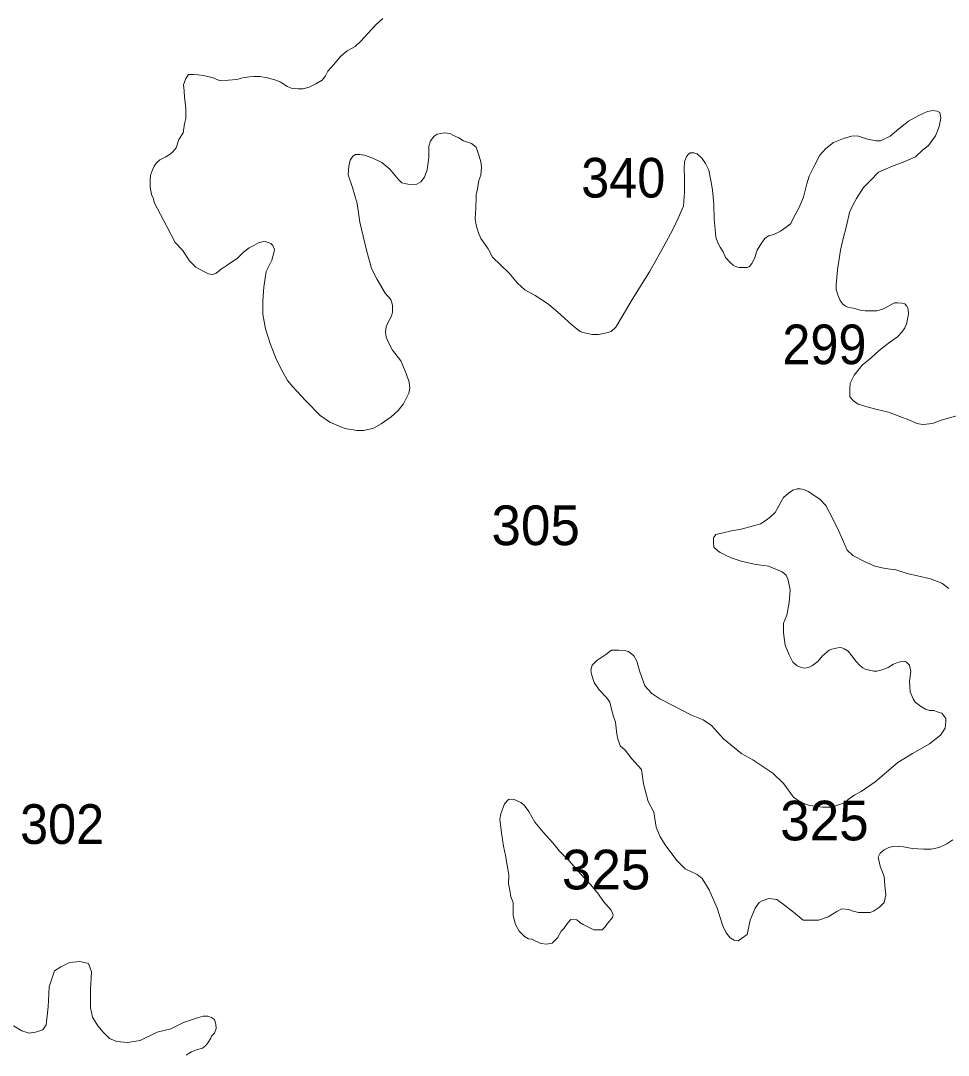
# Model space of a CAD drawing. Extents: x 445.4 to 500, y 8728.7 to 8784.
# Drawn here: x 451.345 to 455.087, y 8728.683 to 8732.857 of the extents above; entities that cross this region are included whole.
import ezdxf

# ---------------------------------------------------------------- set-up
doc = ezdxf.new("R2010")
doc.units = 0
doc.header["$LTSCALE"] = 0.064
doc.layers.add('2', color=7, linetype='Continuous', lineweight=13)
doc.layers.add('21', color=7, linetype='Continuous')

msp = doc.modelspace()

# ---------------------------------------------------------------- linework, layer by layer
at = {"layer": '2'}
for points in [[(452.8059, 8732.8655), (452.7772, 8732.84), (452.7453, 8732.805), (452.7166, 8732.7748), (452.6943, 8732.7525), (452.6624, 8732.735), (452.6369, 8732.7143), (452.6073, 8732.6783), (452.5834, 8732.6529), (452.5738, 8732.6338), (452.5611, 8732.6163), (452.5356, 8732.602), (452.5085, 8732.5892), (452.4846, 8732.5813), (452.4638, 8732.5813), (452.4399, 8732.5829), (452.4192, 8732.5908), (452.3937, 8732.6083), (452.3698, 8732.6179), (452.3411, 8732.6258), (452.3092, 8732.6322), (452.2852, 8732.6322), (452.2677, 8732.6306), (452.2406, 8732.6258), (452.2167, 8732.6195)], [(452.2167, 8732.6195), (452.1832, 8732.6163), (452.1497, 8732.6147), (452.121, 8732.6258), (452.0827, 8732.6354), (452.0588, 8732.6386), (452.0424, 8732.6399), (452.0212, 8732.6399), (452.0106, 8732.6229), (452.0021, 8732.5974), (452.0042, 8732.5741), (452.0063, 8732.5487), (452.0084, 8732.5275), (452.0106, 8732.4999), (452.0106, 8732.4618), (452.0063, 8732.4406), (451.9999, 8732.4045), (451.9829, 8732.3769), (451.9716, 8732.3442), (451.9588, 8732.3273), (451.9472, 8732.3178), (451.9303, 8732.3072), (451.9059, 8732.2956), (451.8921, 8732.284), (451.8837, 8732.2702), (451.8763, 8732.2554), (451.8689, 8732.2333), (451.8667, 8732.2121), (451.8678, 8732.1846), (451.872, 8732.1551), (451.8805, 8732.1382), (451.8837, 8732.1234), (451.9341, 8732.0259), (451.9681, 8731.9623), (451.9978, 8731.9305), (452.0254, 8731.8881), (452.0509, 8731.8627), (452.0807, 8731.8457), (452.1019, 8731.8351), (452.1189, 8731.833), (452.1316, 8731.8372), (452.1529, 8731.8542), (452.1784, 8731.8711), (452.2197, 8731.8981), (452.2432, 8731.9225), (452.2666, 8731.941), (452.2852, 8731.9498), (452.3048, 8731.9605), (452.3184, 8731.9644), (452.3311, 8731.9654), (452.339, 8731.9634), (452.3536, 8731.9585), (452.3624, 8731.9498), (452.3693, 8731.9332), (452.3663, 8731.9205), (452.3575, 8731.8912), (452.3458, 8731.8669), (452.3351, 8731.8444), (452.3311, 8731.8181), (452.3263, 8731.782), (452.3214, 8731.7264), (452.3213, 8731.6726), (452.3319, 8731.6133), (452.351, 8731.5539), (452.3765, 8731.4882), (452.402, 8731.4394), (452.4211, 8731.4055), (452.4424, 8731.38), (452.4955, 8731.3228), (452.5531, 8731.2645), (452.5914, 8731.2369), (452.653, 8731.2115), (452.7018, 8731.203), (452.7294, 8731.203), (452.7677, 8731.2136), (452.7995, 8731.2306), (452.8399, 8731.2581), (452.8675, 8731.2836), (452.8888, 8731.3112), (452.91, 8731.3536), (452.9142, 8731.3748), (452.9121, 8731.3981), (452.8994, 8731.4341), (452.8781, 8731.485), (452.8441, 8731.5274), (452.8295, 8731.5564), (452.8189, 8731.5797), (452.8168, 8731.601), (452.8189, 8731.6222), (452.8274, 8731.6412), (452.8401, 8731.6646), (452.8444, 8731.6815), (452.8444, 8731.6942), (452.8444, 8731.7091), (452.838, 8731.7324), (452.8147, 8731.7578), (452.7828, 8731.813), (452.7594, 8731.8575), (452.7403, 8731.9317), (452.7127, 8732.0441), (452.702, 8732.1198)], [(454.285, 8731.8657), (454.2945, 8731.8779), (454.3054, 8731.8968), (454.3162, 8731.9307), (454.3325, 8731.9592), (454.3461, 8731.9781), (454.361, 8731.989), (454.3828, 8731.9944), (454.4099, 8732.0079), (454.4371, 8732.0269), (454.452, 8732.0391), (454.4615, 8732.0621), (454.4832, 8732.1), (454.5022, 8732.1448), (454.5162, 8732.1984), (454.5257, 8732.2296), (454.5488, 8732.2756), (454.5678, 8732.3149), (454.5922, 8732.3406), (454.6234, 8732.365), (454.6642, 8732.3813), (454.6967, 8732.3908), (454.7198, 8732.3921), (454.7402, 8732.3853), (454.7605, 8732.3786), (454.7958, 8732.3718), (454.8135, 8732.3718), (454.8525, 8732.3904), (454.8872, 8732.4207), (454.9263, 8732.4511), (454.9676, 8732.4749), (455.0023, 8732.4901), (455.0241, 8732.4944), (455.0414, 8732.4923), (455.0523, 8732.4858), (455.0566, 8732.4641), (455.0501, 8732.4294), (455.0349, 8732.3925), (455.0067, 8732.3535), (454.9828, 8732.334), (454.9546, 8732.308), (454.9111, 8732.2885), (454.8568, 8732.269), (454.8047, 8732.2451), (454.7721, 8732.2126), (454.7439, 8732.1845), (454.7157, 8732.1389), (454.7013, 8732.1124), (454.6887, 8732.0834), (454.6761, 8732.0292), (454.6615, 8731.9731), (454.6518, 8731.9305), (454.6401, 8731.8511), (454.6344, 8731.7907), (454.6339, 8731.7722), (454.6414, 8731.7506), (454.6497, 8731.7306), (454.6555, 8731.7206), (454.6631, 8731.7123), (454.6739, 8731.7048), (454.6814, 8731.7015), (454.6939, 8731.699), (454.7047, 8731.6965), (454.7139, 8731.694), (454.7239, 8731.6907), (454.7314, 8731.689), (454.7397, 8731.6873), (454.7514, 8731.6857), (454.7631, 8731.6857), (454.7756, 8731.6857), (454.7989, 8731.6865), (454.8248, 8731.6948), (454.8523, 8731.7098), (454.8689, 8731.7181), (454.8814, 8731.7189), (454.8989, 8731.7173), (454.9106, 8731.7139), (454.919, 8731.7048), (454.9248, 8731.6931), (454.9256, 8731.6732), (454.9223, 8731.654), (454.9198, 8731.6366), (454.9114, 8731.6183), (454.8998, 8731.6), (454.8823, 8731.5817), (454.8453, 8731.5561), (454.8073, 8731.5257), (454.7749, 8731.4972), (454.7388, 8731.4669), (454.7065, 8731.427), (454.6913, 8731.3947), (454.6894, 8731.37), (454.6894, 8731.3397), (454.7046, 8731.3226), (454.7236, 8731.3093), (454.7635, 8731.2979), (454.7997, 8731.2884), (454.8453, 8731.277), (454.891, 8731.2599), (454.9271, 8731.2467), (454.9594, 8731.2315)], [(452.702, 8732.1198), (452.6829, 8732.1834), (452.6659, 8732.2343), (452.668, 8732.2703), (452.6744, 8732.2936), (452.685, 8732.3106), (452.6956, 8732.317), (452.7126, 8732.317), (452.7317, 8732.3148), (452.7657, 8732.3021), (452.8018, 8732.2851), (452.8337, 8732.2576), (452.8677, 8732.2173), (452.8826, 8732.2025), (452.9187, 8732.194), (452.9399, 8732.1961), (452.959, 8732.2067), (452.9739, 8732.2258), (452.9845, 8732.2555), (452.9909, 8732.3042), (452.9909, 8732.3509), (452.9973, 8732.3721), (453.0121, 8732.3912), (453.0249, 8732.3996), (453.0397, 8732.4018), (453.0546, 8732.4039), (453.0759, 8732.4018), (453.0907, 8732.3933), (453.112, 8732.3848), (453.1311, 8732.3721), (453.163, 8732.3615), (453.1821, 8732.3466), (453.1948, 8732.3106), (453.2015, 8732.288), (453.203, 8732.267), (453.2015, 8732.234), (453.1925, 8732.2116), (453.188, 8732.1786), (453.182, 8732.1546), (453.182, 8732.1322), (453.1805, 8732.1142), (453.1805, 8732.0962), (453.179, 8732.0827), (453.1775, 8732.0558), (453.1805, 8732.0393), (453.185, 8732.0228), (453.191, 8732.0003), (453.2015, 8731.9779), (453.212, 8731.9629), (453.23, 8731.9359), (453.248, 8731.9029), (453.3146, 8731.8387), (453.3486, 8731.7985), (453.3784, 8731.7709), (453.4208, 8731.7476), (453.4739, 8731.7136), (453.5228, 8731.6712), (453.5695, 8731.6288), (453.6014, 8731.6034), (453.612, 8731.5992), (453.6503, 8731.5907), (453.6757, 8731.5907), (453.7076, 8731.597), (453.7267, 8731.6034), (453.7458, 8731.6204), (453.7713, 8731.6628), (453.8117, 8731.7327), (453.8818, 8731.843), (453.9392, 8731.9469), (453.9757, 8732.0138), (453.997, 8732.0605), (454.0182, 8732.1092), (454.0224, 8732.1644), (454.0224, 8732.2237), (454.0218, 8732.2607), (454.0231, 8732.2873), (454.0307, 8732.3089), (454.0396, 8732.3203), (454.0459, 8732.3241), (454.0599, 8732.3241), (454.0739, 8732.319), (454.0942, 8732.3013), (454.1069, 8732.281), (454.1208, 8732.2531), (454.1284, 8732.2126), (454.1361, 8732.1746), (454.1411, 8732.1151), (454.1424, 8732.0555), (454.1466, 8732.0161), (454.1493, 8731.9835), (454.1574, 8731.9605), (454.1669, 8731.9429), (454.1778, 8731.9239), (454.1873, 8731.9009), (454.2063, 8731.8819), (454.2185, 8731.8711), (454.228, 8731.8657), (454.243, 8731.8616), (454.2552, 8731.8616), (454.2755, 8731.8616), (454.285, 8731.8657)], [(454.9594, 8731.2315), (454.9842, 8731.2277), (455.0222, 8731.2315), (455.0583, 8731.2448), (455.1249, 8731.2637)], [(455.0882, 8730.5664), (455.0605, 8730.5883), (455.0153, 8730.6057), (454.9672, 8730.6159), (454.9205, 8730.6261), (454.8753, 8730.6421), (454.8316, 8730.6465), (454.7908, 8730.6562), (454.7519, 8730.6744), (454.7015, 8730.6996), (454.6786, 8730.7202), (454.6603, 8730.7636), (454.6397, 8730.8093), (454.6076, 8730.8733), (454.5923, 8730.901), (454.5698, 8730.9255), (454.5443, 8730.9431), (454.5208, 8730.9578), (454.5061, 8730.9636), (454.4972, 8730.9666), (454.4884, 8730.9676), (454.4767, 8730.9676), (454.459, 8730.9627), (454.4423, 8730.9509), (454.4218, 8730.9333), (454.411, 8730.9147), (454.4031, 8730.8991), (454.3884, 8730.8727), (454.3698, 8730.855), (454.3522, 8730.8423)], [(454.3522, 8730.8423), (454.3296, 8730.8276), (454.301, 8730.819), (454.2514, 8730.8057), (454.2122, 8730.7995), (454.1782, 8730.7912), (454.1493, 8730.784), (454.139, 8730.7707), (454.139, 8730.7521), (454.1411, 8730.7336), (454.1565, 8730.7181), (454.1669, 8730.712), (454.1875, 8730.7006), (454.2112, 8730.6903), (454.2514, 8730.677), (454.303, 8730.6646), (454.3618, 8730.6564), (454.4159, 8730.6334), (454.433, 8730.6202), (454.4406, 8730.5993), (454.4482, 8730.5614), (454.4444, 8730.5103), (454.4349, 8730.4591), (454.4216, 8730.4269), (454.4216, 8730.3872), (454.4292, 8730.3379), (454.4444, 8730.2981), (454.4595, 8730.2697), (454.4766, 8730.2545), (454.4936, 8730.2471), (454.5056, 8730.2453), (454.5223, 8730.2481), (454.539, 8730.2555), (454.5604, 8730.2721), (454.5789, 8730.2944), (454.6058, 8730.3175), (454.6169, 8730.3212), (454.6411, 8730.3268), (454.6541, 8730.3277), (454.667, 8730.3231), (454.6828, 8730.3138), (454.6977, 8730.2944), (454.7153, 8730.2721), (454.7301, 8730.2555), (454.7422, 8730.2462), (454.7515, 8730.2407), (454.7867, 8730.2332), (454.7988, 8730.2332), (454.8146, 8730.2369), (454.8266, 8730.2407), (454.8443, 8730.2481), (454.8656, 8730.261), (454.886, 8730.2694), (454.9112, 8730.273), (454.9195, 8730.2675), (454.9305, 8730.2564), (454.9361, 8730.2316), (454.9305, 8730.193), (454.9333, 8730.1489), (454.9443, 8730.1213), (454.9526, 8730.1075), (454.9747, 8730.091), (454.9941, 8730.08), (455.0107, 8730.0744), (455.03, 8730.0744), (455.041, 8730.0689), (455.0604, 8730.0634), (455.0687, 8730.0524), (455.077, 8730.0413), (455.077, 8730.0303), (455.0742, 8730.0027), (455.0549, 8729.9752), (455.0107, 8729.9393), (454.9416, 8729.9007), (454.8836, 8729.8648), (454.7916, 8729.7858), (454.7356, 8729.7475), (454.7089, 8729.7332), (454.6822, 8729.7148), (454.672, 8729.7025), (454.6392, 8729.6922), (454.6166, 8729.6841), (454.5797, 8729.6841), (454.5469, 8729.6881), (454.5243, 8729.6922), (454.4936, 8729.7025), (454.4628, 8729.725), (454.4238, 8729.7782), (454.3787, 8729.8212), (454.2987, 8729.8744), (454.2536, 8729.899), (454.1798, 8729.9604), (454.1308, 8730.0137), (454.0976, 8730.0358), (454.0507, 8730.0551), (453.9761, 8730.0937), (453.9236, 8730.1213), (453.8904, 8730.1433), (453.8628, 8730.1737), (453.8407, 8730.2344), (453.8296, 8730.273)], [(453.8296, 8730.273), (453.8186, 8730.295), (453.7965, 8730.3116), (453.7854, 8730.3143), (453.7578, 8730.3171), (453.7274, 8730.3171), (453.7053, 8730.3005), (453.6694, 8730.2757), (453.65, 8730.2564), (453.6445, 8730.2371), (453.6473, 8730.2206), (453.6583, 8730.1875), (453.6777, 8730.1571), (453.7081, 8730.1268), (453.7219, 8730.1075), (453.7274, 8730.0799), (453.7357, 8730.0496), (453.744, 8730.0275), (453.7467, 8730.0027), (453.7495, 8729.9806), (453.7523, 8729.9641), (453.7633, 8729.931), (453.7827, 8729.9145), (453.8103, 8729.8786), (453.849, 8729.8356), (453.8573, 8729.7777), (453.8763, 8729.7074), (453.8982, 8729.6637), (453.9079, 8729.603), (453.9249, 8729.5641), (453.9468, 8729.5277), (453.9931, 8729.4673), (454.0255, 8729.435), (454.074, 8729.4124), (454.0934, 8729.3962), (454.1226, 8729.351), (454.1549, 8729.2767), (454.1776, 8729.2056), (454.1905, 8729.1766), (454.2067, 8729.1572), (454.2229, 8729.1475), (454.2391, 8729.1443), (454.252, 8729.154), (454.2747, 8729.1701), (454.2876, 8729.2283), (454.307, 8729.2767), (454.3232, 8729.2993), (454.3361, 8729.3058), (454.362, 8729.3155), (454.3944, 8729.3122), (454.4203, 8729.2929), (454.4623, 8729.2606), (454.5012, 8729.2283), (454.5271, 8729.2283), (454.5627, 8729.2283), (454.6015, 8729.2412), (454.6371, 8729.2638), (454.6565, 8729.2735), (454.6858, 8729.2716), (454.7024, 8729.2645), (454.7237, 8729.2598), (454.7426, 8729.2598), (454.771, 8729.2598), (454.7852, 8729.2645), (454.8089, 8729.281), (454.8278, 8729.2999), (454.8349, 8729.3306), (454.8302, 8729.3684), (454.8278, 8729.4039), (454.8112, 8729.4464), (454.8041, 8729.4818), (454.8112, 8729.4983), (454.8278, 8729.5125), (454.8467, 8729.522), (454.868, 8729.5267), (454.9059, 8729.5243), (454.9414, 8729.5172), (454.9864, 8729.5149), (455.0171, 8729.5149), (455.0503, 8729.522), (455.081, 8729.5361), (455.1047, 8729.5527)], [(451.3155, 8728.8024), (451.3496, 8728.7812), (451.3794, 8728.7727), (451.405, 8728.7769), (451.4348, 8728.7854), (451.4476, 8728.8067), (451.4561, 8728.879), (451.4604, 8728.9597), (451.4817, 8729.0235), (451.5072, 8729.0405), (451.5413, 8729.0575), (451.5839, 8729.0618), (451.618, 8729.0533), (451.6308, 8729.0193), (451.6265, 8728.947), (451.6265, 8728.8747), (451.635, 8728.8364), (451.6563, 8728.8024), (451.6776, 8728.7769), (451.7032, 8728.7514), (451.733, 8728.7387), (451.7756, 8728.7344), (451.8267, 8728.7429), (451.8949, 8728.7769), (451.9503, 8728.7897), (452.0014, 8728.8152), (452.0628, 8728.8357), (452.0812, 8728.8407), (452.0996, 8728.8407), (452.1147, 8728.8357), (452.1264, 8728.8273), (452.1314, 8728.809), (452.1331, 8728.7906), (452.1264, 8728.7722), (452.1163, 8728.7622), (452.1113, 8728.7522), (452.0996, 8728.7338), (452.0912, 8728.7221), (452.0778, 8728.7121), (452.0544, 8728.7054), (452.0343, 8728.697), (452.0209, 8728.6887), (452.013, 8728.6831)]]:
    msp.add_lwpolyline(points, dxfattribs=at)
msp.add_lwpolyline([(453.3331, 8729.7168), (453.3119, 8729.7146), (453.2966, 8729.6976), (453.2812, 8729.6572), (453.2773, 8729.636), (453.285, 8729.5802), (453.2927, 8729.5263), (453.3004, 8729.4897), (453.3139, 8729.4108), (453.312, 8729.3742), (453.312, 8729.3742), (453.3177, 8729.3492), (453.3216, 8729.3223), (453.3312, 8729.2992), (453.3312, 8729.2684), (453.3312, 8729.2472), (453.3408, 8729.2106), (453.3562, 8729.1837), (453.3774, 8729.1625), (453.3928, 8729.1529), (453.4063, 8729.151), (453.4429, 8729.1336), (453.466, 8729.1317), (453.489, 8729.1356), (453.5102, 8729.1567), (453.5256, 8729.1837), (453.5352, 8729.1952), (453.5506, 8729.2164), (453.5634, 8729.2303), (453.588, 8729.2294), (453.6007, 8729.2183), (453.6142, 8729.2106), (453.6565, 8729.1895), (453.6903, 8729.1898), (453.7027, 8729.201), (453.7123, 8729.2145), (453.7316, 8729.2395), (453.7342, 8729.25), (453.7267, 8729.268), (453.6964, 8729.3036), (453.6753, 8729.3328), (453.6445, 8729.3713), (453.6026, 8729.4146), (453.5583, 8729.4666), (453.5179, 8729.507), (453.4911, 8729.5405), (453.4525, 8729.5833), (453.4193, 8729.6234), (453.3943, 8729.6663), (453.3756, 8729.6918), (453.3619, 8729.7034)], close=True, dxfattribs=at)

# ---------------------------------------------------------------- texts
at = {"layer": '21', "width": 0.95}
for s, p in [('340', (453.6058, 8732.1432)), ('299', (454.4172, 8731.471)), ('302', (451.3424, 8729.5359))]:
    msp.add_text(s, height=0.16, dxfattribs=at).set_placement(p)
at = {"layer": '21'}
for s, p in [('305', (453.2437, 8730.7411)), ('325', (454.4085, 8729.5501)), ('325', (453.5281, 8729.3524))]:
    msp.add_text(s, height=0.16, dxfattribs=at).set_placement(p)

doc.saveas('drawing.dxf')
